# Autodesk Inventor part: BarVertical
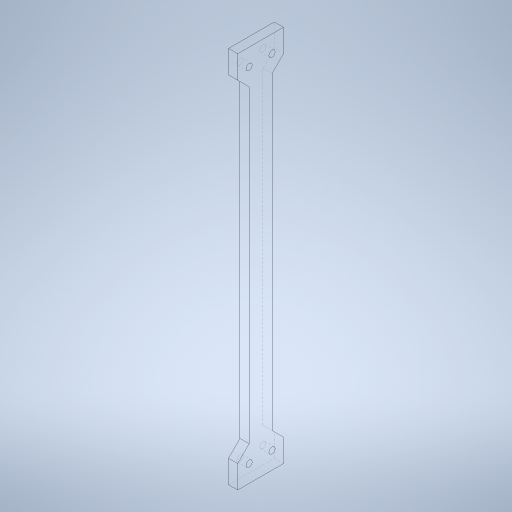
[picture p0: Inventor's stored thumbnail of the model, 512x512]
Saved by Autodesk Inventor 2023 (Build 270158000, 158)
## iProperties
Created: 2023-10
Part Number: BarVertical
Material: Aluminum 7075
Document SubType Name: Modeling
Designer: tornqvih
Density: 2.81 g/cm^3
Appearance: Satin - Brushed Heavy
Author: tornqvih
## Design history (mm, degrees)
sketch "Sketch1"
  geometry: L1 (165, 20)-(165, -20); L2 (165, -20)-(145, -20); L3 (145, -20)-(135, -10); L4 (135, -10)-(-135, -10); L5 (-135, -10)-(-145, -20); L6 (-145, -20)-(-165, -20); L7 (-165, -20)-(-165, 20); L8 (-165, 20)-(-145, 20); L9 (-145, 20)-(-135, 10); L10 (-135, 10)-(135, 10); L11 (135, 10)-(145, 20); L12 (145, 20)-(165, 20); L13 (0, -28)-(0, 28) reference; L14 (-231, 0)-(231, 0) reference; 1 further point
  constraints: 24 end point, 9 symmetric about line, 1 horizontal
  dimensions: "d0" = 20 distance of L2.end L1.end; "d1" = 20 distance between parallel lines of L4 L10; "d2" = 40 distance of L1.start L1.end; "d3" = 290 distance of L5.end L2.end; "d18" = 45 deg angle of L4 L3
extrude "Extrusion1" new body sketch "Sketch1" distance "d5" = 8; taper "d6" = 0 deg
sketch "Sketch2"
  geometry: L1 (28, 0)-(-28, 0) reference; L2 (0, -231)-(0, 231) reference; L3 (20, 145)-(20, 165) reference; L4 (20, 165)-(-20, 165) reference; 5 further points
  constraints: 3 symmetric about line
  dimensions: "d19" = 5 vertical distance of L3.start point (10, 150); "d20" = 10 distance from line of L2 point (10, 150)
hole "Hole1" sketch "Sketch2" at (10, 150), (-10, 150), (10, -150), (-10, -150) diameter "d9" = 5.5; stored, may be unused: countersink angle "d13" = 90 deg, drill point angle "d15" = 118 deg; dims "d10" = 6, "d11" = 4, "d12" = 2, "d14" = 8
body "Solid1"
